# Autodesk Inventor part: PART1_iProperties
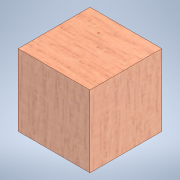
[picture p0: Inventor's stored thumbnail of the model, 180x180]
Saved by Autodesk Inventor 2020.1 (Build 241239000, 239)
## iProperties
Created: 2019-11
Part Number: PART1_iProperties
Material: Wood (Oak)
Document SubType Name: Modeling
Designer: Synergysoft Dell02
Density: 0.76 g/cm^3
Appearance: White Oak - Natural Medium Gloss
Mass: 95 g
Surface Area: 150 cm^2
Volume: 125 cm^3
Author: Synergysoft Dell02
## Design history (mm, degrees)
sketch "Sketch1"
  geometry: L1 (25, 25)-(-25, 25); L2 (-25, 25)-(-25, -25); L3 (-25, -25)-(25, -25); L4 (25, -25)-(25, 25); L5 (25, 25)-(-25, -25); L6 (-25, 25)-(25, -25); 1 further point
  constraints: 12 end point, 2 midpoint, 2 parallel, 1 horizontal, 1 perpendicular
  dimensions: "d0" = 50 distance of L3.end L2.end; "d1" = 50 distance of L2.end L1.end
extrude "Extrusion1" new body sketch "Sketch1" distance "d2" = 50; taper "d3" = 0 deg
body "Solid1"
